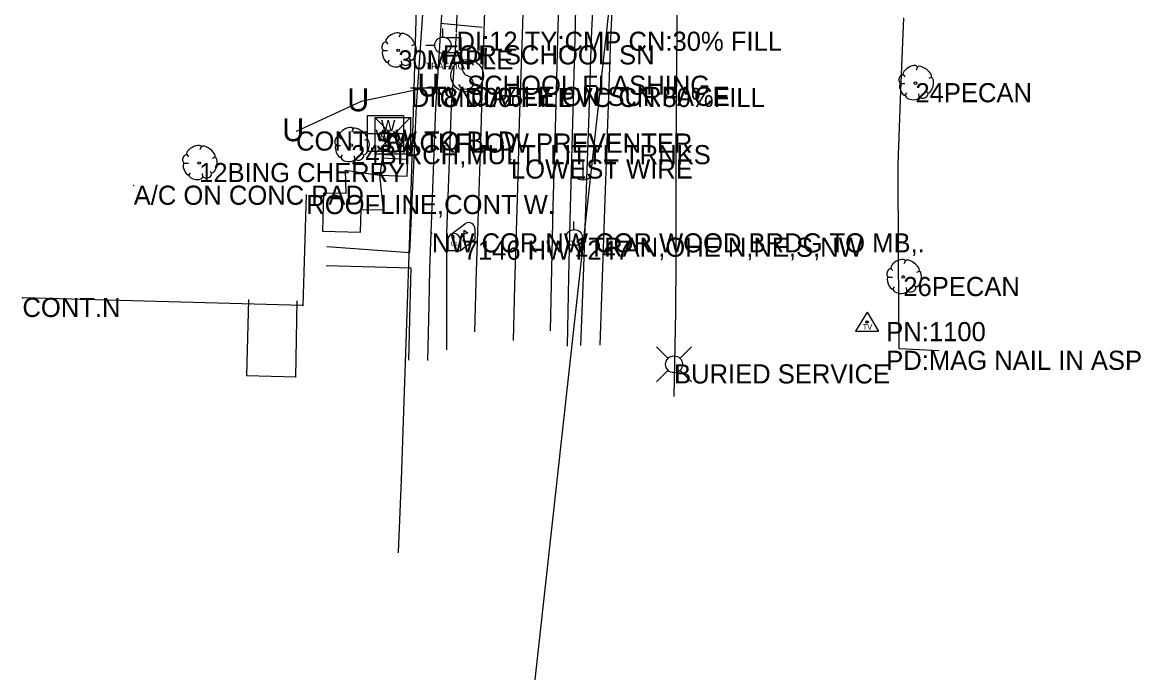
# Model space of a CAD drawing. Extents: x 997398 to 1003416, y 334596 to 337085.
# Drawn here: x 999102.8 to 999393.6, y 334938.7 to 335108.7 of the extents above; entities that cross this region are included whole.
import ezdxf

# ---------------------------------------------------------------- set-up
doc = ezdxf.new("R2010")
doc.units = 0
for name, color, linetype in [('Default', 7, 'Continuous'), ('S_BUILDING', 7, 'Continuous'), ('S_BUILDING_ANNOT', 7, 'Continuous'), ('S_DITCHLINE', 7, 'Continuous'), ('S_DRG_PT_SYM', 7, 'Continuous'), ('S_DRIVEWAY', 7, 'Continuous'), ('S_EDGE_CONCRETE', 7, 'Continuous'), ('S_EDGE_PAVEMENT', 7, 'Continuous'), ('S_ELECTRIC_UTILITIES_ANNOT', 7, 'Continuous'), ('S_GAS_UTILITIES', 7, 'Continuous'), ('S_GRD_PT_SYM', 7, 'Continuous'), ('S_MAILBOX', 7, 'Continuous'), ('S_MAILBOX_ANNOT', 7, 'Continuous'), ('S_MISC_STRUCTURES_ANNOT', 7, 'Continuous'), ('S_MSC_PT_SYM', 7, 'Continuous'), ('S_PAVEMENT_CROWN', 7, 'Continuous'), ('S_SECONDARY_CTL', 7, 'Continuous'), ('S_SECONDARY_CTL_ANNOT', 7, 'Continuous'), ('S_SIDE_DRAIN', 7, 'Continuous'), ('S_SIDE_DRAIN_ANNOT', 7, 'Continuous'), ('S_SIDEWALK', 7, 'Continuous'), ('S_SIGN', 7, 'Continuous'), ('S_SIGN_ANNOT', 7, 'Continuous'), ('S_STR_PT_SYM', 7, 'Continuous'), ('S_TREE', 7, 'Continuous'), ('S_TREE_ANNOT', 7, 'Continuous'), ('S_UNDERGROUND_CABLE', 7, 'Continuous'), ('S_UNDERGROUND_CABLE_ANNOT', 7, 'Continuous'), ('S_UTILITY_POLE', 7, 'Continuous'), ('S_UTILITY_POLE_ANNOT', 7, 'Continuous'), ('S_UTL_PT_SYM', 7, 'Continuous'), ('S_WATER_UTILITIES', 7, 'Continuous'), ('S_WATER_UTILITIES_ANNOT', 7, 'Continuous')]:
    doc.layers.add(name, color=color, linetype=linetype)

msp = doc.modelspace()

# ---------------------------------------------------------------- linework, layer by layer
at = {"layer": 'Default'}
msp.add_line((999206.9, 334665.47), (999272.07, 335256.17), dxfattribs=at)
at = {"layer": 'S_BUILDING'}
for p, q in [((999177, 335063.58), (999176.11, 335034.68)), ((999176.11, 335034.68), (999102.8, 335036.68))]:
    msp.add_line(p, q, dxfattribs=at)
at = {"layer": 'S_DITCHLINE'}
for points in [[(999252.77, 335245.59), (999251.64, 335223.38), (999250.51, 335201.16), (999249.91, 335187.35), (999249.3, 335173.53), (999248.31, 335151.72), (999247.75, 335128.15), (999247.19, 335104.58), (999246.61, 335082.45), (999246.03, 335060.31), (999245.59, 335042.2), (999245.16, 335024.09)], [(999213.78, 335023.12), (999213.75, 335038.37), (999213.72, 335053.62), (999214.34, 335070.11), (999214.95, 335086.6), (999216.24, 335105.71)]]:
    msp.add_lwpolyline(points, dxfattribs=at)
at = {"layer": 'S_DRG_PT_SYM'}
for points in [[(999216.27, 335106.26), (999216.27, 335106.31), (999216.27, 335106.26), (999216.22, 335106.26), (999216.27, 335106.26), (999216.27, 335106.21), (999216.27, 335106.26), (999216.32, 335106.26)], [(999204.35, 335091.57), (999204.35, 335091.62), (999204.35, 335091.57), (999204.3, 335091.57), (999204.35, 335091.57), (999204.35, 335091.52), (999204.35, 335091.57), (999204.4, 335091.57)], [(999211.87, 335091.56), (999211.87, 335091.61), (999211.87, 335091.56), (999211.82, 335091.56), (999211.87, 335091.56), (999211.87, 335091.51), (999211.87, 335091.56), (999211.92, 335091.56)]]:
    msp.add_lwpolyline(points, dxfattribs=at)
at = {"layer": 'S_DRIVEWAY'}
msp.add_lwpolyline([(999222.94, 335107.33), (999212.12, 335108.37)], dxfattribs=at)
at = {"layer": 'S_EDGE_CONCRETE'}
for points in [[(999203.53, 335072.89), (999196.82, 335073.16), (999196.26, 335068.8), (999203.36, 335068.53)], [(999203.36, 335068.53), (999203.53, 335072.89)], [(999187.13, 335070.05), (999187.33, 335063.97), (999181.49, 335064.08), (999181.25, 335054.15), (999191.19, 335053.88), (999191.34, 335059.78), (999197.21, 335059.68)], [(999187.13, 335070.05), (999196.26, 335068.8)], [(999197.21, 335059.68), (999196.26, 335068.8)]]:
    msp.add_lwpolyline(points, dxfattribs=at)
at = {"layer": 'S_EDGE_PAVEMENT'}
for points in [[(999221.03, 335027.81), (999221.44, 335040.9), (999221.86, 335053.99), (999222.28, 335067.08), (999222.7, 335080.18), (999223.11, 335093.27), (999223.53, 335106.36), (999223.95, 335119.45), (999224.36, 335132.54), (999225.08, 335153.24), (999225.79, 335173.94), (999226.53, 335190.42), (999227.27, 335206.91), (999228, 335223.39), (999228.74, 335239.88), (999229.57, 335253.09), (999230.4, 335266.31), (999231.23, 335279.53), (999232.05, 335292.74)], [(999253.37, 335256.43), (999249.78, 335251.63), (999248.81, 335243.39), (999247.69, 335222.16), (999246.57, 335200.94), (999245.83, 335187.38), (999245.09, 335173.83), (999244.51, 335155.82), (999243.66, 335131.7), (999242.8, 335107.59), (999242.11, 335084.06), (999241.43, 335060.53), (999241.09, 335044.29), (999240.74, 335028.05)], [(999325.44, 335135.07), (999324.44, 335132.45), (999301.88, 335129.85), (999288.01, 335129.01), (999274.14, 335128.17), (999273.91, 335107.32), (999273.67, 335086.47), (999273.64, 335073.11), (999273.61, 335059.74), (999273.58, 335046.38), (999273.55, 335033.02), (999273.11, 335010.86)], [(999331.73, 335071.66), (999332.45, 335090.76), (999333.17, 335109.85)], [(999342.41, 335022.81), (999331.99, 335023.36), (999331.86, 335047.51), (999331.73, 335071.66)]]:
    msp.add_lwpolyline(points, dxfattribs=at)
at = {"layer": 'S_GAS_UTILITIES'}
for p, q in [((999206.76, 335147.2), (999204.1, 335055.65)), ((999204.1, 335055.65), (999201.84, 334989.08)), ((999201.84, 334989.08), (999201.01, 334970.18))]:
    msp.add_line(p, q, dxfattribs=at)
at = {"layer": 'S_GRD_PT_SYM'}
msp.add_lwpolyline([(999230.51, 335072.86), (999230.51, 335072.91), (999230.51, 335072.86), (999230.46, 335072.86), (999230.51, 335072.86), (999230.51, 335072.81), (999230.51, 335072.86), (999230.56, 335072.86)], dxfattribs=at)
at = {"layer": 'S_MAILBOX'}
for p, q in [((999214.53, 335053.08), (999218.67, 335056.19)), ((999218.15, 335054.37), (999218.15, 335051.66)), ((999221.1, 335054.72), (999221.1, 335052)), ((999213.98, 335051.81), (999213.98, 335049.09)), ((999217.3, 335049.09), (999221.1, 335052)), ((999217.3, 335051.81), (999217.3, 335049.09)), ((999213.98, 335049.09), (999217.3, 335049.09))]:
    msp.add_line(p, q, dxfattribs=at)
for points in [[(999218.15, 335054.37), (999219.25, 335053.71), (999218.15, 335053.36)], [(999215.16, 335052.92), (999215.38, 335052.78), (999215.38, 335052.4), (999215.69, 335052.4), (999215.69, 335052.76), (999215.49, 335053.01), (999215.16, 335052.95)]]:
    msp.add_lwpolyline(points, dxfattribs=at)
for centre, end in [((999219.44, 335054.72), 117.5718), ((999215.64, 335051.81), 180)]:
    msp.add_arc(centre, 1.66, 0, end, dxfattribs=at)
msp.add_ellipse((999218.15, 335051.66), major_axis=(0.145, 0.132), ratio=0.564646, dxfattribs=at)
at = {"layer": 'S_MSC_PT_SYM'}
for points in [[(999131.89, 335066.02), (999131.89, 335066.07), (999131.89, 335066.02), (999131.84, 335066.02), (999131.89, 335066.02), (999131.89, 335065.97), (999131.89, 335066.02), (999131.94, 335066.02)], [(999209.8, 335053.56), (999209.8, 335053.61), (999209.8, 335053.56), (999209.75, 335053.56), (999209.8, 335053.56), (999209.8, 335053.51), (999209.8, 335053.56), (999209.85, 335053.56)]]:
    msp.add_lwpolyline(points, dxfattribs=at)
at = {"layer": 'S_PAVEMENT_CROWN'}
msp.add_lwpolyline([(999231.13, 335025.58), (999231.54, 335039.84), (999231.96, 335054.1), (999232.37, 335068.37), (999232.78, 335082.63), (999233.49, 335105.48), (999234.2, 335128.32), (999234.91, 335151.16), (999235.62, 335174.01), (999236.52, 335191.6), (999237.42, 335209.19), (999238.19, 335224.55), (999238.95, 335239.91), (999239.44, 335245.85), (999240.93, 335269.15), (999242.42, 335292.45)], dxfattribs=at)
at = {"layer": 'S_SECONDARY_CTL'}
for p, q in [((999323.62, 335032.97), (999320.61, 335028.02)), ((999323.62, 335032.97), (999326.57, 335028.02)), ((999320.61, 335028.02), (999326.57, 335028.02))]:
    msp.add_line(p, q, dxfattribs=at)
for radius in [0.311, 0.183, 0.103]:
    msp.add_circle((999323.62, 335030.36), radius, dxfattribs=at)
at = {"layer": 'S_SIDE_DRAIN'}
for p, q in [((999216.27, 335106.26), (999217.15, 335130.27)), ((999204.35, 335091.57), (999211.87, 335091.56))]:
    msp.add_line(p, q, dxfattribs=at)
at = {"layer": 'S_SIDEWALK'}
for points in [[(999182.37, 335050.08), (999204.11, 335048.56), (999204.95, 335067.66), (999205.79, 335086.76), (999207.41, 335109.65), (999209.03, 335132.54), (999210.52, 335153.41), (999212, 335174.28), (999213.15, 335190.71), (999214.3, 335207.14), (999215.44, 335223.58), (999216.59, 335240.01), (999220.56, 335249.46), (999220.79, 335269.72), (999214.01, 335280.58), (999214.8, 335292.62)], [(999208.77, 335020.35), (999209.1, 335034.73), (999209.29, 335044.2), (999210.06, 335065.27), (999210.83, 335086.34), (999212.37, 335109.29), (999213.9, 335132.24), (999215.27, 335153.19), (999216.64, 335174.15), (999217.76, 335190.41), (999218.88, 335206.67), (999220.01, 335222.94), (999221.13, 335239.2), (999224.96, 335248.97), (999225.73, 335271.38), (999218.89, 335281.67)], [(999255.18, 335201.13), (999254.88, 335187.29), (999254.58, 335173.44), (999253.96, 335155.96), (999253.34, 335143.12), (999252.73, 335130.28), (999252.11, 335117.44), (999251.5, 335104.6), (999250.76, 335082.39), (999250.02, 335060.17), (999249.36, 335042.19), (999248.7, 335024.21)], [(999260.19, 335201.09), (999259.85, 335187.19), (999259.51, 335173.29), (999261.77, 335173.24), (999261.91, 335173.2), (999273.63, 335172.94), (999275.99, 335173.22), (999275.89, 335169.08), (999273.44, 335169.51), (999261.84, 335169.89), (999259.26, 335169.84), (999258.98, 335159.99), (999265.32, 335159.89), (999265.3, 335155.88), (999258.79, 335155.99), (999258.23, 335143.09), (999257.67, 335130.2), (999257.11, 335117.3), (999256.56, 335104.4), (999255.74, 335082.14), (999254.93, 335059.88), (999254.31, 335042.1), (999253.7, 335024.32)], [(999203.82, 335020.41), (999204.12, 335034.63), (999204.42, 335044.43), (999182.16, 335045.1)], [(999174.49, 335035.9), (999174.16, 335015.99), (999161.46, 335016.29), (999161.95, 335036.24)]]:
    msp.add_lwpolyline(points, dxfattribs=at)
at = {"layer": 'S_SIGN'}
msp.add_circle((999219.05, 335094.77), 4.24, dxfattribs=at)
for centre, radius, start, end in [((999219.18, 335096.92), 1.62, 16.5258, 156.8957), ((999220.22, 335097.02), 2.55, 167.1196, 241.9813), ((999218.79, 335093.37), 2.17, 204.641, 335.359), ((999218.35, 335092.49), 2.38, 358.6529, 73.7063)]:
    msp.add_arc(centre, radius, start, end, dxfattribs=at)
at = {"layer": 'S_STR_PT_SYM'}
for points in [[(999177, 335063.58), (999177, 335063.63), (999177, 335063.58), (999176.95, 335063.58), (999177, 335063.58), (999177, 335063.53), (999177, 335063.58), (999177.05, 335063.58)], [(999102.8, 335036.68), (999102.8, 335036.73), (999102.8, 335036.68), (999102.75, 335036.68), (999102.8, 335036.68), (999102.8, 335036.63), (999102.8, 335036.68), (999102.85, 335036.68)], [(999176.11, 335034.68), (999176.11, 335034.73), (999176.11, 335034.68), (999176.06, 335034.68), (999176.11, 335034.68), (999176.11, 335034.63), (999176.11, 335034.68), (999176.16, 335034.68)]]:
    msp.add_lwpolyline(points, dxfattribs=at)
at = {"layer": 'S_TREE'}
for p, q in [((999201.6, 335105.64), (999201.21, 335104.79)), ((999197.14, 335101.3), (999198.26, 335101.3)), ((999197.8, 335103.62), (999198.3, 335103.04)), ((999205.16, 335102.85), (999204.5, 335102.58)), ((999198.3, 335098.12), (999198.77, 335098.82)), ((999201.98, 335097.85), (999201.91, 335098.63)), ((999204.39, 335098.74), (999203.92, 335099.17)), ((999333, 335095.04), (999333.51, 335094.46)), ((999336.8, 335097.06), (999336.41, 335096.21)), ((999332.34, 335092.72), (999333.47, 335092.72)), ((999340.37, 335094.27), (999339.71, 335094)), ((999333.51, 335089.54), (999333.97, 335090.24)), ((999337.19, 335089.27), (999337.11, 335090.05)), ((999339.59, 335090.16), (999339.13, 335090.59)), ((999189.3, 335080.86), (999188.91, 335080.01)), ((999185.5, 335078.85), (999186, 335078.27)), ((999192.86, 335078.07), (999192.2, 335077.8)), ((999149.54, 335076.19), (999149.15, 335075.34)), ((999184.84, 335076.52), (999185.96, 335076.52)), ((999145.08, 335071.85), (999146.21, 335071.85)), ((999145.74, 335074.17), (999146.24, 335073.59)), ((999153.1, 335073.4), (999152.44, 335073.13)), ((999186, 335073.35), (999186.47, 335074.04)), ((999189.68, 335073.08), (999189.61, 335073.85)), ((999192.09, 335073.97), (999191.62, 335074.39)), ((999146.24, 335068.67), (999146.71, 335069.37)), ((999149.93, 335068.4), (999149.85, 335069.18)), ((999152.33, 335069.29), (999151.86, 335069.72)), ((999333.62, 335046.4), (999333.24, 335045.55)), ((999329.83, 335044.38), (999330.33, 335043.8)), ((999337.19, 335043.61), (999336.53, 335043.34)), ((999329.17, 335042.06), (999330.29, 335042.06)), ((999336.41, 335039.5), (999335.95, 335039.93)), ((999330.33, 335038.88), (999330.8, 335039.58)), ((999334.01, 335038.61), (999333.93, 335039.39))]:
    msp.add_line(p, q, dxfattribs=at)
for centre in [(999201.04, 335101.39), (999336.24, 335092.81), (999188.74, 335076.62), (999148.98, 335071.94), (999333.07, 335042.15)]:
    msp.add_circle(centre, 0.341, dxfattribs=at)
for centre, major_axis, ratio, start_param, end_param in [((999199.7, 335104.6), (1.86, 1.08), 0.471018, 0, 3.141593), ((999203.36, 335104.27), (-1.81, 1.36), 0.405113, 3.141593, 6.283186), ((999197.47, 335102.48), (0.31, 1.03), 0.646762, 0, 3.141593), ((999197.77, 335099.83), (-0.61, 1.6), 0.420543, 6.283185, 9.424777), ((999204.71, 335100.86), (0.46, 2.04), 0.482994, 3.141593, 6.283185), ((999200.23, 335098.05), (-1.83, 0.19), 0.529943, 0, 3.141593), ((999203.19, 335098.34), (1.09, 0.46), 0.711534, 3.141592, 6.283185), ((999332.67, 335093.9), (0.31, 1.03), 0.646762, 0, 3.141593), ((999334.91, 335096.02), (1.86, 1.08), 0.471018, 0, 3.141593), ((999338.56, 335095.69), (-1.81, 1.36), 0.405113, 3.141593, 6.283186), ((999332.98, 335091.25), (-0.61, 1.6), 0.420543, 6.283185, 9.424777), ((999339.92, 335092.28), (0.46, 2.04), 0.482994, 3.141593, 6.283185), ((999335.44, 335089.47), (-1.83, 0.19), 0.529943, 0, 3.141593), ((999338.4, 335089.76), (1.09, 0.46), 0.711534, 3.141592, 6.283185), ((999187.4, 335079.82), (1.86, 1.08), 0.471018, 0, 3.141593), ((999191.06, 335079.5), (-1.81, 1.36), 0.405113, 3.141593, 6.283186), ((999185.17, 335077.71), (0.31, 1.03), 0.646762, 0, 3.141593), ((999192.41, 335076.09), (0.46, 2.04), 0.482994, 3.141593, 6.283185), ((999147.64, 335075.15), (1.86, 1.08), 0.471018, 0, 3.141593), ((999151.3, 335074.82), (-1.81, 1.36), 0.405113, 3.141593, 6.283186), ((999185.47, 335075.06), (-0.61, 1.6), 0.420543, 6.283185, 9.424777), ((999145.41, 335073.03), (0.31, 1.03), 0.646762, 0, 3.141593), ((999145.71, 335070.38), (-0.61, 1.6), 0.420543, 6.283185, 9.424777), ((999152.65, 335071.41), (0.46, 2.04), 0.482994, 3.141593, 6.283185), ((999187.93, 335073.28), (-1.83, 0.19), 0.529943, 0, 3.141593), ((999190.89, 335073.57), (1.09, 0.46), 0.711534, 3.141592, 6.283185), ((999151.13, 335068.89), (1.09, 0.46), 0.711534, 3.141592, 6.283185), ((999148.17, 335068.6), (-1.83, 0.19), 0.529943, 0, 3.141593), ((999331.73, 335045.36), (1.86, 1.08), 0.471018, 0, 3.141593), ((999335.39, 335045.03), (-1.81, 1.36), 0.405113, 3.141593, 6.283186), ((999329.5, 335043.24), (0.31, 1.03), 0.646762, 0, 3.141593), ((999336.74, 335041.62), (0.46, 2.04), 0.482994, 3.141593, 6.283185), ((999329.8, 335040.59), (-0.61, 1.6), 0.420543, 6.283185, 9.424777), ((999332.26, 335038.81), (-1.83, 0.19), 0.529943, 0, 3.141593), ((999335.22, 335039.1), (1.09, 0.46), 0.711534, 3.141592, 6.283185)]:
    msp.add_ellipse(centre, major_axis=major_axis, ratio=ratio, start_param=start_param, end_param=end_param, dxfattribs=at)
at = {"layer": 'S_UNDERGROUND_CABLE'}
for p, q in [((999209.65, 335091.85), (999191.32, 335087.98)), ((999191.32, 335087.98), (999174.33, 335080.18))]:
    msp.add_line(p, q, dxfattribs=at)
at = {"layer": 'S_UTILITY_POLE'}
for p, q in [((999212.71, 335104.81), (999212.71, 335107.06)), ((999217.51, 335104.66), (999213.64, 335104.66)), ((999217.51, 335100.75), (999217.51, 335104.66)), ((999210.61, 335102.68), (999208.29, 335102.68)), ((999212.78, 335098.26), (999212.78, 335100.59)), ((999217.51, 335100.75), (999213.64, 335100.75)), ((999249.27, 335072.3), (999249.27, 335067.57)), ((999246.96, 335054.56), (999246.96, 335056.67)), ((999271.54, 335020.89), (999268.56, 335023.87)), ((999274.72, 335020.89), (999277.7, 335023.87)), ((999271.54, 335017.71), (999268.56, 335014.73)), ((999274.72, 335017.71), (999277.7, 335014.73))]:
    msp.add_line(p, q, dxfattribs=at)
for centre, radius in [((999212.71, 335102.7), 2.13), ((999247.08, 335052.42), 2.13), ((999273.14, 335019.31), 2.21)]:
    msp.add_circle(centre, radius, dxfattribs=at)
msp.add_arc((999249.33, 335070.99), 3.41, 226.3972, 313.6028, dxfattribs=at)
at = {"layer": 'S_UTL_PT_SYM'}
for points in [[(999230.51, 335072.86), (999230.51, 335072.91), (999230.51, 335072.86), (999230.46, 335072.86), (999230.51, 335072.86), (999230.51, 335072.81), (999230.51, 335072.86), (999230.56, 335072.86)], [(999204.1, 335055.65), (999204.1, 335055.7), (999204.1, 335055.65), (999204.05, 335055.65), (999204.1, 335055.65), (999204.1, 335055.6), (999204.1, 335055.65), (999204.15, 335055.65)], [(999201.84, 334989.08), (999201.84, 334989.13), (999201.84, 334989.08), (999201.79, 334989.08), (999201.84, 334989.08), (999201.84, 334989.03), (999201.84, 334989.08), (999201.89, 334989.08)], [(999201.01, 334970.18), (999201.01, 334970.23), (999201.01, 334970.18), (999200.96, 334970.18), (999201.01, 334970.18), (999201.01, 334970.13), (999201.01, 334970.18), (999201.06, 334970.18)]]:
    msp.add_lwpolyline(points, dxfattribs=at)
at = {"layer": 'S_WATER_UTILITIES'}
for p, q in [((999192.97, 335084.34), (999202.38, 335084.34)), ((999192.97, 335074.93), (999192.97, 335084.34)), ((999194.91, 335083.86), (999204.25, 335083.86)), ((999194.91, 335083.86), (999194.91, 335074.37)), ((999194.91, 335083.86), (999204.25, 335074.37)), ((999204.25, 335083.86), (999194.91, 335074.37)), ((999202.38, 335084.34), (999202.38, 335074.93)), ((999204.25, 335083.86), (999204.25, 335074.37)), ((999192.97, 335079.65), (999202.38, 335079.65)), ((999202.38, 335074.93), (999192.97, 335074.93)), ((999194.91, 335074.37), (999204.25, 335074.37))]:
    msp.add_line(p, q, dxfattribs=at)

# ---------------------------------------------------------------- texts
at = {"layer": 'S_BUILDING_ANNOT'}
for s, p in [('ROOFLINE,CONT W.', (999177, 335058.58)), ('CONT.N', (999102.8, 335031.68))]:
    msp.add_text(s, height=5, dxfattribs=at).set_placement(p)
at = {"layer": 'S_ELECTRIC_UTILITIES_ANNOT'}
msp.add_text('LOWEST WIRE', height=5, dxfattribs=at).set_placement((999230.51, 335067.86))
at = {"layer": 'S_MAILBOX'}
msp.add_text('US', height=0.96, rotation=360, dxfattribs=at).set_placement((999214.74, 335050.29))
at = {"layer": 'S_MAILBOX_ANNOT'}
msp.add_text('7146 HWY247', height=5, dxfattribs=at).set_placement((999218.15, 335046.66))
at = {"layer": 'S_MISC_STRUCTURES_ANNOT'}
for s, p in [('A/C ON CONC PAD', (999131.89, 335061.02)), ('NW COR NW COR WOOD BRDG TO MB,.', (999209.8, 335048.56))]:
    msp.add_text(s, height=5, dxfattribs=at).set_placement(p)
at = {"layer": 'S_SECONDARY_CTL'}
msp.add_text('TV', height=1.5, rotation=360, dxfattribs=at).set_placement((999322.42, 335028.35))
at = {"layer": 'S_SECONDARY_CTL_ANNOT'}
for s, p in [('PN:1100', (999328.62, 335025.36)), ('PD:MAG NAIL IN ASPH', (999328.62, 335017.86))]:
    msp.add_text(s, height=5, dxfattribs=at).set_placement(p)
at = {"layer": 'S_SIDE_DRAIN_ANNOT'}
for s, p in [('DI:12 TY:CMP CN:30% FILL', (999216.27, 335101.26)), ('DI:8 DI:6 TY:PVC CN:80%FILL', (999204.35, 335086.57)), ('CN:0%FILL', (999211.87, 335086.56))]:
    msp.add_text(s, height=5, dxfattribs=at).set_placement(p)
at = {"layer": 'S_SIGN_ANNOT'}
msp.add_text('SCHOOL,FLASHING', height=5, dxfattribs=at).set_placement((999219.05, 335089.77))
at = {"layer": 'S_TREE_ANNOT'}
for s, p in [('30MAPLE', (999201.04, 335096.39)), ('24PECAN', (999336.24, 335087.81)), ('24BIRCH,MULTI LITTL TRNKS', (999188.74, 335071.62)), ('12BING CHERRY', (999148.98, 335066.94)), ('26PECAN', (999333.07, 335037.15))]:
    msp.add_text(s, height=5, dxfattribs=at).set_placement(p)
at = {"layer": 'S_UNDERGROUND_CABLE_ANNOT'}
for s, p in [('TV CABLE ON SURFACE', (999209.65, 335086.85)), ('CONT.SW TO BLD', (999174.33, 335075.18))]:
    msp.add_text(s, height=5, dxfattribs=at).set_placement(p)
at = {"layer": 'S_UTILITY_POLE'}
msp.add_text('TRAFFIC', height=1.8, rotation=360, dxfattribs=at).set_placement((999208.13, 335096.39))
at = {"layer": 'S_UTILITY_POLE_ANNOT'}
for s, p in [('FOR SCHOOL SN', (999212.71, 335097.7)), ('1TRAN,OHE N,NE,S,NW', (999247.08, 335047.42)), ('BURIED SERVICE', (999273.14, 335014.31))]:
    msp.add_text(s, height=5, dxfattribs=at).set_placement(p)
at = {"layer": 'S_UTL_PT_SYM'}
for p in [(999206.02, 335089.31), (999187.69, 335085.44), (999170.7, 335077.63)]:
    msp.add_text('U', height=6, rotation=360, dxfattribs=at).set_placement(p)
at = {"layer": 'S_WATER_UTILITIES'}
for s, p in [('W M', (999195.12, 335077.63)), ('W', (999196.52, 335080.19)), ('V', (999196.75, 335076.12))]:
    msp.add_text(s, height=3, rotation=360, dxfattribs=at).set_placement(p)
at = {"layer": 'S_WATER_UTILITIES_ANNOT'}
msp.add_text('BACKFLOW PREVENTER', height=5, dxfattribs=at).set_placement((999197.68, 335074.65))

doc.saveas('drawing.dxf')
